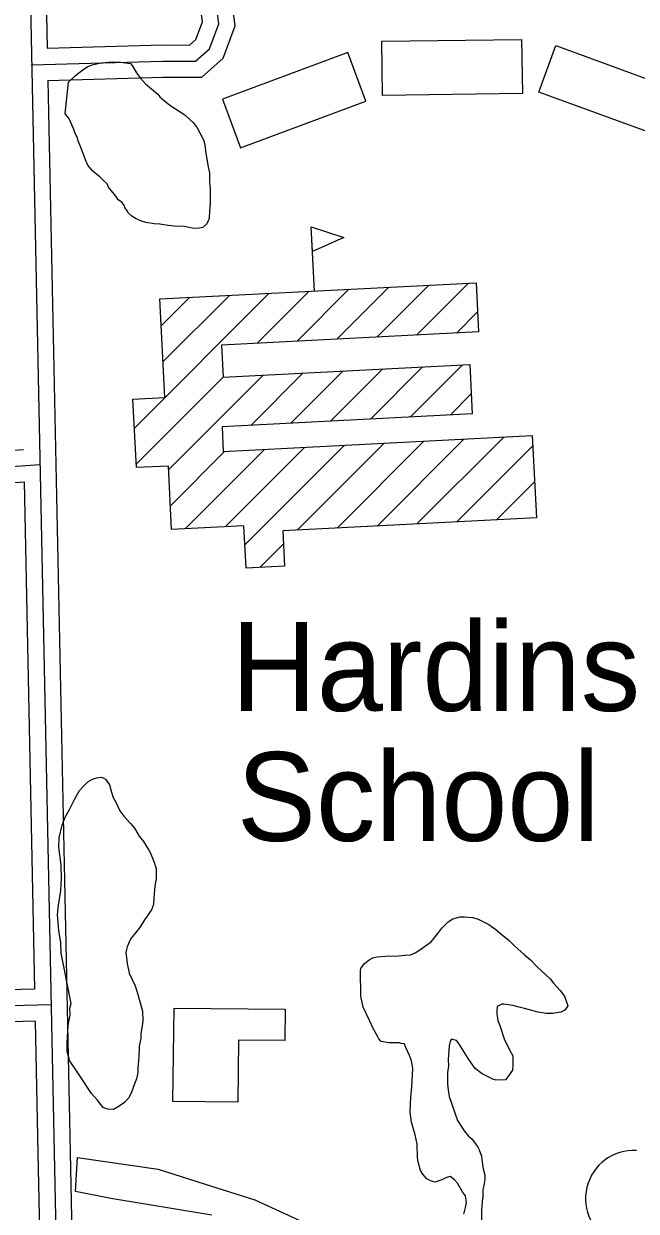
# Model space of a CAD drawing. Extents: x 3313442 to 3351311, y 721974 to 747360.
# Drawn here: x 3332487 to 3333060, y 736117 to 737227 of the extents above; entities that cross this region are included whole.
import ezdxf

# ---------------------------------------------------------------- set-up
doc = ezdxf.new("R2010")
doc.units = 0
for name, color, linetype in [('V-BLDG-IDEN', 7, 'Continuous'), ('V-BLDG-OTLN', 7, 'Continuous'), ('V-ROAD-CNTR', 7, 'Continuous'), ('V-SITE-VEGE', 7, 'Continuous'), ('V-TOPO-SHOR', 7, 'Continuous')]:
    doc.layers.add(name, color=color, linetype=linetype)

msp = doc.modelspace()

# ---------------------------------------------------------------- linework, layer by layer
at = {"layer": 'V-BLDG-OTLN'}
for p, q in [((3332758.6, 736976.7), (3332755.5, 737036.6)), ((3332854.1, 736935.5), (3332902.7, 736984.1)), ((3332590.2, 736848.4), (3332716.4, 736974.6)), ((3332617, 736910.5), (3332679.1, 736972.6)), ((3332705, 736927.9), (3332753.6, 736976.5)), ((3332742.3, 736929.8), (3332790.9, 736978.4)), ((3332779.6, 736931.7), (3332828.2, 736980.3)), ((3332816.8, 736933.6), (3332865.5, 736982.2)), ((3332615.2, 736944.1), (3332641.8, 736970.7)), ((3332891.4, 736937.4), (3332911.2, 736957.2)), ((3332848.2, 736858.9), (3332897, 736907.7)), ((3332591.9, 736814.8), (3332673.4, 736896.2)), ((3332622.3, 736809.7), (3332710.6, 736898.1)), ((3332699.1, 736851.2), (3332747.9, 736900)), ((3332736.4, 736853.2), (3332785.2, 736901.9)), ((3332773.7, 736855.1), (3332822.4, 736903.9)), ((3332810.9, 736857), (3332859.7, 736905.8)), ((3332885.5, 736860.8), (3332905.2, 736880.6)), ((3332854.4, 736759), (3332935.6, 736840.2)), ((3332637.8, 736754.5), (3332711.9, 736828.7)), ((3332675, 736756.4), (3332749.2, 736830.6)), ((3332693.6, 736739.6), (3332786.5, 736832.5)), ((3332742.6, 736753.3), (3332823.7, 736834.4)), ((3332779.8, 736755.2), (3332861, 736836.4)), ((3332817.1, 736757.1), (3332898.3, 736838.3)), ((3332891.7, 736760.9), (3332962.8, 736832)), ((3332624, 736776.1), (3332674.6, 736826.8)), ((3332928.9, 736762.9), (3332964.5, 736798.4)), ((3332707.6, 736718.3), (3332729.7, 736740.4))]:
    msp.add_line(p, q, dxfattribs=at)
for points in [[(3332953, 737161.2), (3332822.3, 737159.5), (3332821.6, 737210.2), (3332952.3, 737211.9)], [(3333083, 737120.8), (3332968.3, 737162.7), (3332984.2, 737206.2), (3333098.9, 737164.2)], [(3332789.8, 737199.6), (3332672.6, 737156.1), (3332689.5, 737110.7), (3332806.6, 737154.2)], [(3332755.5, 737036.6), (3332786, 737026.7), (3332756.7, 737013.6)], [(3332966.2, 736764.8), (3332729, 736752.6), (3332730.7, 736719.5), (3332694.7, 736717.7), (3332692.7, 736757.3), (3332625.1, 736753.9), (3332622.1, 736813.2), (3332592.1, 736811.7), (3332588.8, 736875.6), (3332618.7, 736877.2), (3332613.9, 736969.3), (3332909.8, 736984.5), (3332912.1, 736938.5), (3332671.8, 736926.2), (3332673.4, 736896.2), (3332903.8, 736908), (3332906.2, 736861.9), (3332672.2, 736849.9), (3332673.4, 736826.7), (3332962.3, 736841.6)], [(3332626.2, 736219.2), (3332627.3, 736306.6), (3332731.3, 736305.4), (3332731, 736276.2), (3332687.6, 736276.7), (3332686.9, 736218.5)]]:
    msp.add_lwpolyline(points, close=True, dxfattribs=at)
at = {"layer": 'V-ROAD-CNTR'}
for points in [[(3332393.3, 741750), (3332433.1, 739875.2), (3332463.5, 738663.9), (3332515.1, 736171.2), (3332527.9, 735558.8)], [(3332494.1, 737187.9), (3332494.1, 737188.1), (3332616.8, 737191.7), (3332647.5, 737191.6), (3332660.5, 737203.1), (3332669.2, 737226.5), (3332655.4, 737331), (3332656.1, 737439)], [(3332504.2, 737424.8), (3332508.7, 737203.6)], [(3332508.7, 737203.6), (3332616.6, 737206.7), (3332641.8, 737206.6), (3332647.7, 737211.9), (3332653.8, 737228.2), (3332640.3, 737330.1), (3332641, 737424)], [(3332509.4, 737173.6), (3332617, 737176.7), (3332653.2, 737176.6), (3332673.2, 737194.4), (3332684.5, 737224.7), (3332670.4, 737331.9), (3332671, 737424.9)], [(3332509.4, 737173.6), (3332530.1, 736171.5), (3332542.5, 735577.5)], [(3332497.5, 736294.3), (3332212.9, 736287), (3332191.9, 736303.7), (3332186.6, 736334.2), (3332175.4, 736777.6), (3332180.4, 736802.3), (3332200, 736808.3), (3332486.5, 736828.5)], [(3332512.2, 736309.7), (3332217.9, 736302.1), (3332205.7, 736311.9), (3332201.5, 736335.7), (3332190.5, 736776.3), (3332193.3, 736790.6), (3332202.7, 736793.4), (3332501.8, 736814.6)], [(3332496.9, 736324.3), (3332223, 736317.3), (3332219.5, 736320), (3332216.5, 736337.2), (3332205.5, 736775), (3332206.3, 736778.8), (3332205.5, 736778.6), (3332487.1, 736798.5)], [(3332487.1, 736798.5), (3332496.9, 736324.3)], [(3332497.5, 736294.3), (3332500.1, 736170.9), (3332512.6, 735573.8)]]:
    msp.add_lwpolyline(points, dxfattribs=at)
msp.add_arc((3333057.3, 736128.4), 45.2, 86.7505, 45.0708, dxfattribs=at)
at = {"layer": 'V-SITE-VEGE'}
for points in [[(3332525.4, 737142.4), (3332528.7, 737172.1), (3332534.9, 737177.8), (3332539.9, 737182), (3332546.1, 737186.2), (3332550.8, 737188), (3332554.9, 737189.2), (3332559.4, 737190.1), (3332569.4, 737191.1), (3332577.4, 737190.6), (3332586.6, 737189.5), (3332588.1, 737187.4), (3332592.3, 737180.6), (3332595.9, 737175.6), (3332600.7, 737170.3), (3332606.1, 737165.6), (3332612.1, 737160.6), (3332614.2, 737158.3), (3332618.3, 737154.4), (3332623.4, 737150.6), (3332637.4, 737141.5), (3332642.5, 737136.6), (3332645.2, 737134.2), (3332648.8, 737129.2), (3332651.5, 737124.5), (3332654.8, 737118), (3332656, 737113.5), (3332656.7, 737107.9), (3332657.6, 737102), (3332659.1, 737092.8), (3332660.4, 737087.2), (3332660.4, 737078.9), (3332661.1, 737072.7), (3332661.2, 737058.7), (3332660.4, 737051.3), (3332660.1, 737044.5), (3332658.1, 737039.4), (3332654.3, 737036.2), (3332649.2, 737035.2), (3332644.2, 737035.5), (3332637.1, 737036.9), (3332627.3, 737037.4), (3332621.9, 737038), (3332613.9, 737039.1), (3332608.6, 737039.6), (3332600.9, 737040.8), (3332597, 737041.9), (3332591.4, 737044.5), (3332587.8, 737046.6), (3332584.8, 737049.5), (3332583.3, 737052.2), (3332581.5, 737054.2), (3332580.6, 737056.6), (3332578.5, 737059.9), (3332575.2, 737061.9), (3332573.1, 737065.1), (3332570.1, 737068.7), (3332566.2, 737073.7), (3332564.7, 737076.9), (3332560.8, 737080.8), (3332557.8, 737083.4), (3332553.7, 737086.9), (3332551, 737089), (3332546.8, 737094.3), (3332544.4, 737099.3), (3332540.4, 737110.2), (3332537.7, 737117), (3332537.1, 737120), (3332535, 737124.1), (3332533.2, 737128.6), (3332529, 737138.3)], [(3332531.2, 736310.7), (3332521.9, 736357.8), (3332521.5, 736367.5), (3332519.6, 736379.1), (3332518.3, 736393.6), (3332519.2, 736402.8), (3332521.4, 736416.5), (3332522.2, 736427.7), (3332521.8, 736440.2), (3332519.6, 736457), (3332519.8, 736465.6), (3332522.7, 736477.5), (3332525.6, 736485), (3332529.7, 736492.1), (3332534.7, 736502.2), (3332539, 736510), (3332542.9, 736514.4), (3332546.7, 736518), (3332551.1, 736520.4), (3332555, 736521.7), (3332559.1, 736522.3), (3332561.2, 736521.7), (3332563.3, 736520.5), (3332566.9, 736515.2), (3332568.1, 736510.5), (3332570.2, 736504), (3332572.9, 736499), (3332576.5, 736491), (3332580.4, 736486), (3332586.7, 736479.2), (3332590.3, 736474.8), (3332594.8, 736467.1), (3332598.7, 736462.1), (3332603.8, 736454.2), (3332605.3, 736451.2), (3332609.2, 736442.1), (3332610.5, 736436.7), (3332610.5, 736427.5), (3332609.4, 736420.7), (3332608.3, 736409.4), (3332608.1, 736403.5), (3332606.3, 736398.5), (3332604.6, 736396.1), (3332602.2, 736392.5), (3332599.6, 736388.9), (3332595.2, 736381.8), (3332587.3, 736371.9), (3332586.1, 736369.8), (3332583.5, 736363.9), (3332582.3, 736358.8), (3332583.6, 736348.2), (3332585.5, 736339.3), (3332590.9, 736327.2), (3332593, 736321.3), (3332597.9, 736303.8), (3332598, 736294.6), (3332597.4, 736289.9), (3332596.3, 736282.8), (3332596.3, 736278), (3332594.6, 736270.9), (3332594.6, 736268.5), (3332594.4, 736261.7), (3332594.1, 736257.3), (3332593.6, 736250.7), (3332593.6, 736246.3), (3332592.2, 736240.4), (3332590.5, 736235.9), (3332587.6, 736227.9), (3332585.2, 736222.8), (3332581.4, 736218.6), (3332578.7, 736216.8), (3332574.6, 736213.8), (3332570.8, 736211.7), (3332565.4, 736212), (3332563.4, 736212.6), (3332561, 736213.7), (3332555.3, 736220.8), (3332550.2, 736226.7), (3332539.1, 736243.2), (3332533.7, 736251.7), (3332529.8, 736257), (3332527.4, 736265.9), (3332527.3, 736274.2), (3332528.4, 736290.2), (3332530.1, 736300.3), (3332530, 736306.6)]]:
    msp.add_lwpolyline(points, close=True, dxfattribs=at)
for points in [[(3332802, 736317.6), (3332801.8, 736341.6), (3332802.1, 736343.7), (3332805, 736347.9), (3332809.8, 736351.5), (3332813.3, 736353.6), (3332817.1, 736354.5), (3332824.9, 736355.2), (3332837.3, 736355.3), (3332843.5, 736355.9), (3332848.3, 736356.2), (3332852.7, 736358.3), (3332856.2, 736360.5), (3332867.7, 736368.5), (3332873.9, 736376.3), (3332877.7, 736381.4), (3332883.6, 736387.1), (3332888, 736390.1), (3332894.8, 736391.9), (3332899, 736391.9), (3332906.7, 736391.1), (3332911.7, 736389.7), (3332919.2, 736385.9), (3332921.8, 736384.7), (3332928.1, 736380), (3332932.6, 736376.2), (3332940.6, 736369.7), (3332945.7, 736364.7), (3332955, 736356.2), (3332960.6, 736351.8), (3332967.2, 736344.7), (3332978.9, 736333.9), (3332982.2, 736329.8), (3332988.4, 736323), (3332992.3, 736317.7), (3332995.4, 736308.8), (3332992.7, 736304.6), (3332988.9, 736302.8), (3332981.5, 736301.6), (3332975.3, 736301.5), (3332967.6, 736302.7), (3332963.1, 736304.1), (3332955.1, 736306.1), (3332950, 736307.3), (3332944.1, 736309), (3332935.8, 736310.1), (3332933.7, 736310.1), (3332929.6, 736308), (3332929, 736304.4), (3332929, 736301.2), (3332930, 736294.9), (3332931.8, 736290.2), (3332936, 736277.8), (3332940.6, 736268.1), (3332944.2, 736261.9), (3332944.2, 736253.6), (3332943.7, 736248.5), (3332940.2, 736243.2), (3332937.2, 736239.6), (3332928.6, 736239.2), (3332925.4, 736240.1), (3332915.3, 736245), (3332909, 736250), (3332903, 736258.6), (3332893.7, 736273.6), (3332891.3, 736276.3), (3332886.8, 736277.4), (3332885.4, 736275.6), (3332884.5, 736271.2), (3332883.7, 736258.4), (3332883.8, 736252.2), (3332882.9, 736246.2), (3332883, 736235.6), (3332883.7, 736229.7), (3332884.6, 736224), (3332892.5, 736201.6), (3332896.4, 736195.4), (3332898.5, 736191.8), (3332902.7, 736186.8), (3332905.7, 736184.2), (3332909.3, 736179.8), (3332911.4, 736176.5), (3332912.6, 736174.2), (3332914.7, 736168.2), (3332915, 736165), (3332916, 736158.2), (3332916.6, 736155.2), (3332917.8, 736150.5), (3332917.8, 736146.3), (3332917, 736140.7), (3332916.1, 736137.1), (3332915.9, 736133.3), (3332915.9, 736130)], [(3332898.2, 736113.9), (3332900, 736120.1), (3332900.8, 736124.9), (3332899.9, 736131.1), (3332896.9, 736134.9), (3332892.4, 736142.9), (3332889.7, 736146.1), (3332885.5, 736149), (3332882.2, 736148.1), (3332877.8, 736146), (3332871.6, 736143.9), (3332867.2, 736145), (3332863.6, 736147.1), (3332860, 736151.2), (3332857.9, 736154.7), (3332855.7, 736163), (3332855.1, 736166.9), (3332854.7, 736179.3), (3332852.9, 736188.2), (3332849.5, 736200), (3332848, 736209.2), (3332848.7, 736223.7), (3332849.6, 736232.6), (3332850.3, 736244.2), (3332850.6, 736250.1), (3332849.4, 736257.2), (3332847.5, 736262.3), (3332843.9, 736270.2), (3332842.7, 736273.2), (3332839.7, 736273.5), (3332837.7, 736274), (3332828.2, 736274), (3332821, 736275.4), (3332818.7, 736277.7), (3332817.7, 736280.4), (3332813.5, 736287.5), (3332810.2, 736294.9), (3332804.2, 736307.3), (3332802, 736317.6)], [(3332915.9, 736130), (3332915.3, 736126.2), (3332915.1, 736121.1), (3332914.8, 736117.9), (3332914.9, 736103.6)]]:
    msp.add_lwpolyline(points, dxfattribs=at)
at = {"layer": 'V-TOPO-SHOR'}
msp.add_lwpolyline([(3332662.7, 736113.1), (3332568.3, 736128.5), (3332535.3, 736135.1), (3332537.2, 736167), (3332612.6, 736156), (3332662.3, 736140), (3332702.8, 736127.2), (3332753.1, 736104.3), (3332791.7, 736074.1), (3332873.8, 736005.9), (3332983.9, 735895.5), (3333012.1, 735873.3), (3333066.6, 735820.5)], dxfattribs=at)

# ---------------------------------------------------------------- texts
at = {"layer": 'V-BLDG-IDEN'}
for s, p in [('Hardins', (3332680.7, 736584.3)), ('School', (3332686, 736462.8))]:
    msp.add_text(s, height=83, dxfattribs=at).set_placement(p)

doc.saveas('drawing.dxf')
